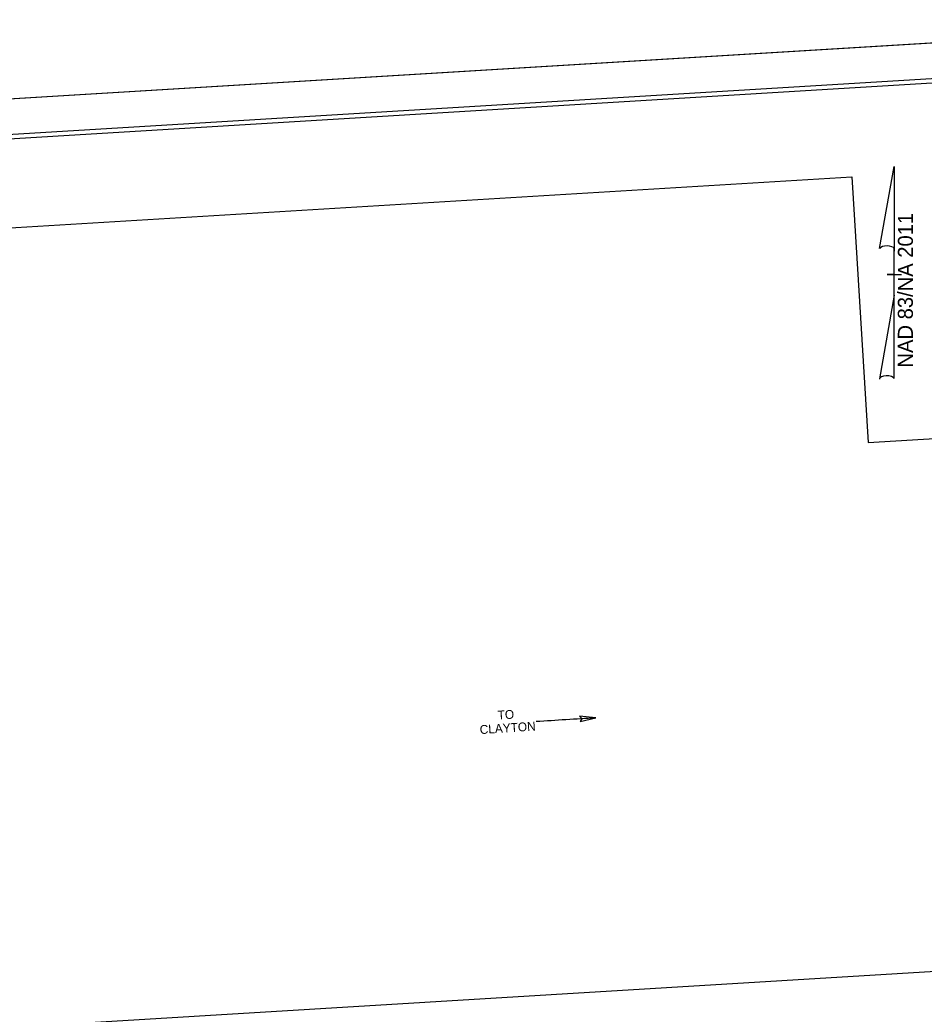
# Model space of a CAD drawing. Extents: x 2111349 to 2114115, y 669753 to 671326.
# Drawn here: x 2113118 to 2113628, y 670387 to 670948 of the extents above; entities that cross this region are included whole.
import ezdxf

# ---------------------------------------------------------------- set-up
doc = ezdxf.new("R2010")
doc.units = 0
for name, color, linetype in [('Exist Other Culture Anchor (Guy Wire) CELL', 7, 'Continuous'), ('Exist Other Culture Sign Text', 7, 'Continuous'), ('Exist Roads Curbs', 7, 'Continuous'), ('Exist Roads Curbs Text', 7, 'Continuous'), ('Exist Roads EOP Other Text', 7, 'Continuous'), ('Exist Utilities TV Test Hole SUE LOS A CELL', 7, 'Continuous'), ('Exist Utilities TV Test Hole SUE LOS A Text', 7, 'Continuous'), ('Exist Utilities Water Fire Hydrant Cogo Number', 7, 'Continuous'), ('Exist Utilities Water Test Hole SUE LOS A Text', 7, 'Continuous')]:
    doc.layers.add(name, color=color, linetype=linetype)

msp = doc.modelspace()

# ---------------------------------------------------------------- linework, layer by layer
at = {"layer": 'Exist Other Culture Sign Text'}
for p, q in [((2113602.74, 670818.64), (2113610.96, 670864.98)), ((2113611.01, 670864.98), (2113610.96, 670864.98)), ((2113611.01, 670864.98), (2113610.96, 670864.98)), ((2113611.01, 670864.98), (2113610.99, 670817.18)), ((2113610.98, 670792.38), (2113610.99, 670818.58)), ((2113610.99, 670817.18), (2113610.99, 670818.53)), ((2113606.98, 670803.99), (2113606.93, 670803.99)), ((2113610.53, 670803.98), (2113606.98, 670803.99)), ((2113607.03, 670803.99), (2113615.03, 670803.98)), ((2113610.98, 670792.38), (2113602.61, 670745.14)), ((2113611.01, 670745.33), (2113610.98, 670792.38))]:
    msp.add_line(p, q, dxfattribs=at)
for centre, start_param, end_param in [((2113606.87, 670818.14), 0.216388, 2.908219), ((2113606.84, 670744.97), 0.201328, 3.141593)]:
    msp.add_ellipse(centre, major_axis=(4.23, -0.03), ratio=0.461098, start_param=start_param, end_param=end_param, dxfattribs=at)
at = {"layer": 'Exist Roads Curbs'}
msp.add_line((2113849.32, 670947.55), (2112168.9, 670845.7), dxfattribs=at)
at = {"layer": 'Exist Roads Curbs Text'}
msp.add_lwpolyline([(2113833.71, 670924.06), (2112336.45, 670833.32), (2112399.97, 669785.24), (2113897.23, 669875.98)], close=True, dxfattribs=at)
at = {"layer": 'Exist Roads EOP Other Text'}
msp.add_lwpolyline([(2112246.91, 669773.46), (2113909.86, 669874.24), (2113846.03, 670927.31), (2112183.08, 670826.53)], close=True, dxfattribs=at)
at = {"layer": 'Exist Utilities TV Test Hole SUE LOS A CELL'}
msp.add_arc((2113787.71, 664813.06), 5751.33, 93.440064, 93.775296, dxfattribs=at)
at = {"layer": 'Exist Utilities TV Test Hole SUE LOS A Text'}
msp.add_lwpolyline([(2112416.61, 670337.26), (2112389.39, 670786.43), (2113587.14, 670859.03), (2113596.22, 670709.25), (2113795.9, 670721.35), (2113814.05, 670421.95)], close=True, dxfattribs=at)
at = {"layer": 'Exist Utilities Water Fire Hydrant Cogo Number'}
msp.add_lwpolyline([(2113433.72, 670551.93), (2113442.61, 670554.02), (2113433.48, 670555.07), (2113434.72, 670553.55)], close=True, dxfattribs=at)
at = {"layer": 'Exist Utilities Water Test Hole SUE LOS A Text'}
msp.add_lwpolyline([(2112235.14, 669752.71), (2113915.56, 669854.55), (2113849.32, 670947.55), (2112168.9, 670845.7)], close=True, dxfattribs=at)

# ---------------------------------------------------------------- texts
at = {"layer": 'Exist Other Culture Anchor (Guy Wire) CELL'}
for s, p in [('TO', (2113387.42, 670553.04)), ('CLAYTON', (2113377.31, 670544.87))]:
    msp.add_text(s, height=5, rotation=3.7331, dxfattribs=at).set_placement(p)
at = {"layer": 'Exist Other Culture Sign Text'}
msp.add_text('NAD 83/NA 2011', height=8.5, rotation=89.9761, dxfattribs=at).set_placement((2113621.48, 670751.55))

doc.saveas('drawing.dxf')
